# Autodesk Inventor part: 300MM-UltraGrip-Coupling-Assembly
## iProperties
Created: 2012-05
Part Number: 300MM-UltraGrip-Coupling-Assembly
Document SubType Name: Modeling
Designer: D Cole
Density: 1 g/cm^3
Author: D Cole
